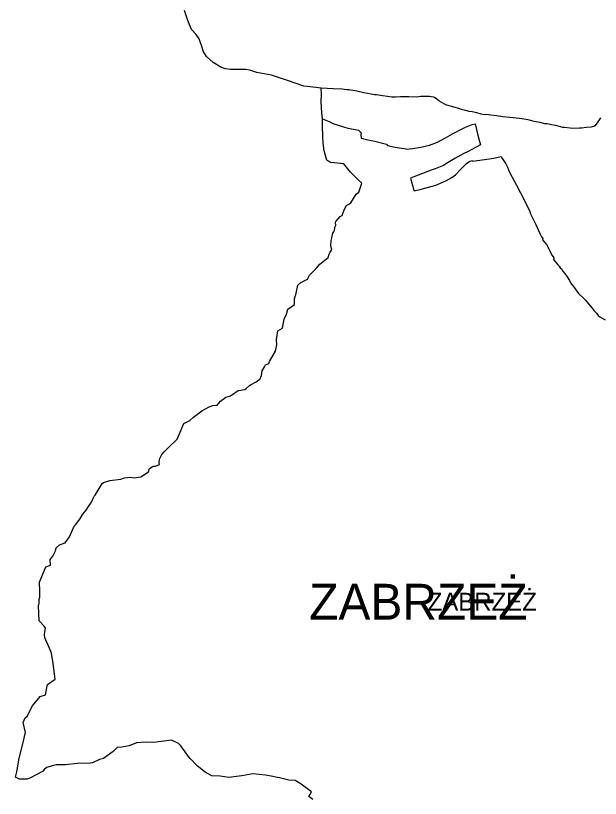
# Model space of a CAD drawing. Extents: x -562952 to -547638, y 190691 to 208158.
# Drawn here: x -562570 to -559633, y 198378 to 202309 of the extents above; entities that cross this region are included whole.
import ezdxf

# ---------------------------------------------------------------- set-up
doc = ezdxf.new("R2010")
doc.units = 0
for name, color, linetype in [('granica_gminy', 7, 'Continuous'), ('granica_sołectwa', 7, 'Continuous'), ('nazwy miejscowości', 7, 'Continuous'), ('nazwy miejscowości DUŻE', 7, 'Continuous'), ('obwódka', 7, 'Continuous')]:
    doc.layers.add(name, color=color, linetype=linetype)

msp = doc.modelspace()

# ---------------------------------------------------------------- linework, layer by layer
at = {"layer": 'granica_gminy'}
msp.add_lwpolyline([(-561077.5, 198371.9), (-561096.6, 198387.6), (-561083.3, 198410), (-561135.6, 198449.1), (-561165.8, 198467.7), (-561197.6, 198469.7), (-561243.6, 198480.3), (-561254.1, 198482.6), (-561287, 198489.2), (-561314.3, 198494.3), (-561378.7, 198500.4), (-561432.9, 198490.8), (-561447.6, 198488.4), (-561498.1, 198482.4), (-561542, 198488.3), (-561584.2, 198491.4), (-561618.4, 198509.3), (-561658.1, 198541.3), (-561692.7, 198577.8), (-561704, 198590.1), (-561709.6, 198600), (-561740.1, 198642.1), (-561751.4, 198653.7), (-561787.4, 198669.6), (-561877, 198657.9), (-561914.9, 198659.3), (-561961.9, 198656.2), (-562000, 198640.9), (-562037, 198634.7), (-562059.7, 198632.3), (-562080, 198612.5), (-562129.3, 198578.4), (-562147.9, 198572.7), (-562184, 198556.7), (-562195.9, 198554.2), (-562261.3, 198552.7), (-562319.6, 198546), (-562353.3, 198545.9), (-562366, 198545.7), (-562387, 198541.1), (-562413.4, 198533), (-562424.9, 198524.3), (-562435.1, 198512.3), (-562495.8, 198481), (-562512.4, 198473.7), (-562551, 198474), (-562569.7, 198484.5), (-562564.2, 198510.5), (-562552.1, 198578.6), (-562529.2, 198670.8), (-562524.3, 198697.2), (-562519.7, 198708.4), (-562531.9, 198759), (-562521.7, 198782.3), (-562512, 198789.8), (-562484.5, 198842.9), (-562447.3, 198889.6), (-562419.1, 198897.7), (-562409.8, 198950), (-562371.2, 198976.2), (-562381.9, 199054.7), (-562389.4, 199106.5), (-562401.7, 199134.5), (-562423.7, 199184.4), (-562424.3, 199201.2), (-562425.6, 199204.1), (-562422.7, 199211.1), (-562422.1, 199221.8), (-562420.1, 199231.8), (-562425.9, 199241.6), (-562451.8, 199269.7), (-562453.4, 199308.8), (-562454.4, 199342.4), (-562452.1, 199358.3), (-562452.1, 199376.1), (-562448.9, 199387.8), (-562448.9, 199418.7), (-562450.2, 199464.1), (-562418, 199539.6), (-562395.3, 199549.6), (-562395.7, 199577.9), (-562382.2, 199594.8), (-562368.7, 199624.7), (-562369.7, 199626.3), (-562365.8, 199635.1), (-562348.8, 199650.5), (-562320.9, 199661.2), (-562299.2, 199690.7), (-562275.2, 199744), (-562268.9, 199751), (-562248.1, 199779.7), (-562232, 199805.4), (-562216.2, 199825), (-562203.6, 199842.8), (-562188.7, 199865.5), (-562176.4, 199891.7), (-562175.8, 199895.6), (-562170.6, 199899.8), (-562136, 199958.9), (-562127.9, 199964.7), (-562096.9, 199974.8), (-562041.6, 199980.3), (-562022.8, 199988), (-561992.3, 199990.5), (-561973.6, 199987.4), (-561940.6, 199991.9), (-561902.1, 200017.2), (-561896.6, 200034.7), (-561883.6, 200043.4), (-561879, 200045.5), (-561867.7, 200046.6), (-561846.9, 200054), (-561849.2, 200062.8), (-561847.5, 200081.5), (-561835.5, 200104.6), (-561823.3, 200118.3), (-561802.3, 200139.2), (-561758.3, 200182.2), (-561724.9, 200260.6), (-561694.9, 200274.6), (-561676.6, 200292.5), (-561634.5, 200324.3), (-561597.6, 200344.8), (-561579.1, 200350.2), (-561557.5, 200352.5), (-561541.3, 200371.8), (-561513.6, 200393.1), (-561490.3, 200399.2), (-561452.8, 200425.9), (-561419, 200431.3), (-561412.2, 200435.4), (-561395.1, 200451.8), (-561387, 200455.9), (-561362.3, 200470.4), (-561344, 200482.3), (-561337.6, 200492.7), (-561334.9, 200502.2), (-561332.2, 200525.2), (-561319.4, 200544.8), (-561315, 200554.6), (-561297.2, 200561.6), (-561293.8, 200572.4), (-561265.1, 200622.8), (-561258.3, 200655.2), (-561260.3, 200681.6), (-561252.8, 200725.8), (-561228.9, 200739.9), (-561220.4, 200785.2), (-561208.6, 200810.2), (-561203.2, 200833.9), (-561169.5, 200858.4), (-561169.1, 200886.5), (-561161, 200914.8), (-561151.9, 200955.1), (-561138, 200968.3), (-561103, 200984.7), (-561094.2, 201006), (-561065.1, 201034.1), (-561060.7, 201038.8), (-561041.4, 201059.8), (-561000.6, 201094.1), (-560995.2, 201111.4), (-560990.8, 201116.8), (-560981.7, 201134), (-560986.5, 201150.5), (-560985.1, 201178.7), (-560981, 201193), (-560977.1, 201216.9), (-560973.1, 201220.7), (-560968.2, 201230.6), (-560966.1, 201240.7), (-560967.5, 201243.1), (-560961.4, 201255.9), (-560962.8, 201267.8), (-560960.8, 201274.2), (-560940.4, 201299.9), (-560929, 201305.4), (-560919.5, 201333.6), (-560908.3, 201354.9), (-560895.3, 201362.2), (-560886.3, 201369.5), (-560858.5, 201411.4), (-560846.4, 201421.6), (-560830.3, 201466.9), (-560847.8, 201482.2), (-560880.8, 201515.7), (-560887.3, 201523.2), (-560921.9, 201564.6), (-560986, 201570.9), (-561002.2, 201580.3), (-561006.1, 201582.7), (-561013.7, 201606.9), (-561021.3, 201636.3), (-561021.6, 201641.6), (-561024.5, 201669.4), (-561026.8, 201700.8), (-561027, 201706), (-561028, 201750.2), (-561029, 201791.4), (-561031.9, 201821.3), (-561035.7, 201876.1), (-561033.9, 201914.4), (-561034.7, 201943.8), (-561104.3, 201952.6), (-561121.7, 201955.4), (-561204.9, 201983.5), (-561283.9, 202009.4), (-561302.4, 202012.7), (-561357.7, 202023.9), (-561394.2, 202034.9), (-561415.3, 202038.1), (-561491.3, 202038.8), (-561515.8, 202041.5), (-561539.8, 202050.1), (-561578.3, 202073.8), (-561611.2, 202103.1), (-561627.6, 202130.9), (-561632.2, 202148.6), (-561648.7, 202192.9), (-561663.3, 202213.4), (-561686.7, 202239.4), (-561705.3, 202285), (-561722.3, 202335.3)], dxfattribs=at)
at = {"layer": 'granica_sołectwa'}
for points in [[(-560702.2, 201902.1), (-560727.2, 201906), (-560746.9, 201909.6), (-560756.6, 201910.4), (-560767.7, 201910.4), (-560783.5, 201914.6), (-560820.9, 201921.5), (-560856.5, 201929), (-560896.9, 201935.5), (-560906.8, 201935.5), (-560919.6, 201938.5), (-560929.2, 201939.4), (-560974.1, 201941.8), (-561034.7, 201943.8)], [(-560343.5, 201842.3), (-560368.1, 201848.9), (-560379.4, 201853), (-560392.3, 201855.4), (-560409.6, 201861.4), (-560420.9, 201867.1), (-560443.9, 201880.9), (-560452.6, 201886.9), (-560462.2, 201896.1), (-560469.4, 201900), (-560481.9, 201901.5), (-560490.3, 201903.6), (-560510.6, 201903.3), (-560535.1, 201903), (-560556.9, 201900), (-560594.2, 201900.3), (-560636.1, 201900.3), (-560661.8, 201899.1), (-560680.9, 201899.7), (-560702.2, 201902.1)], [(-559632.5, 201795), (-559648.3, 201770.8), (-559660.3, 201754.6), (-559665.3, 201751.3), (-559679.1, 201748), (-559704.5, 201747.1), (-559726.1, 201744.1), (-559737.1, 201743.8), (-559772, 201742.3), (-559784.6, 201744.1), (-559813, 201746.8), (-559821.7, 201747.7), (-559856.9, 201756.4), (-559878.4, 201760.3), (-559899.9, 201766.3), (-559911.3, 201766), (-559937.3, 201771.4), (-559955.6, 201774.9), (-559965.7, 201777), (-559988.7, 201784.5), (-560004.9, 201787.2), (-560039.6, 201792.3), (-560087.7, 201796.8), (-560123, 201801.3), (-560154.1, 201804.9), (-560182.8, 201808.5), (-560193, 201810), (-560208.1, 201811.7), (-560216.2, 201810), (-560230.6, 201814.1), (-560253, 201821), (-560276.6, 201825.5), (-560292.2, 201827.9), (-560308.3, 201832.7), (-560325, 201836.3), (-560343.5, 201842.3)], [(-561029, 201791.4), (-560994.8, 201777.7), (-560976.4, 201767.3), (-560923.1, 201749.9), (-560900.6, 201744.5), (-560872.5, 201738), (-560847, 201733.8), (-560834.7, 201719.7), (-560835.9, 201711.3), (-560833.8, 201693.3)], [(-560834.3, 201694), (-560821, 201689.4), (-560800.3, 201684.9), (-560783.2, 201681.6), (-560764.8, 201678.6), (-560707.4, 201663.5), (-560702.6, 201657.4), (-560663.6, 201647.5), (-560610.6, 201639.1), (-560606.3, 201638.9), (-560575.8, 201641.8), (-560534.7, 201648.5), (-560491.2, 201658.8), (-560451.4, 201673.2), (-560410.8, 201695.2), (-560375.5, 201715.4), (-560323.6, 201741.4), (-560310.2, 201748.3), (-560276.2, 201762), (-560262.1, 201766.2), (-560247.4, 201709.3), (-560241.6, 201682.8), (-560234, 201659.3), (-560299.9, 201624.2), (-560318.7, 201616.2), (-560363.3, 201591.1), (-560406.2, 201565.6), (-560420.1, 201557), (-560462.2, 201539.3), (-560482.3, 201532.2), (-560570.2, 201499.9), (-560587, 201492.2), (-560569.3, 201432.9), (-560568.5, 201428.2), (-560532.7, 201436.6), (-560458.7, 201457.3), (-560408.9, 201479.2), (-560378.7, 201495.8), (-560359.8, 201509.3), (-560331.6, 201539.8), (-560304.7, 201566.3), (-560288.8, 201578.3), (-560275.3, 201581.1), (-560273.8, 201577.7), (-560214, 201585.8), (-560168.3, 201593.4), (-560131, 201602.2), (-560124.7, 201589), (-560108, 201565.3), (-560098.9, 201547.1), (-560093.4, 201534.2), (-560085, 201516)], [(-560765.4, 201677.3), (-560765.4, 201677.3)], [(-560085, 201516), (-560054.5, 201458), (-560012.8, 201376.7), (-559999.6, 201352.2), (-559989.2, 201329.5), (-559983.3, 201313.6), (-559957.1, 201259.1), (-559937.1, 201214.8), (-559929, 201198.6), (-559922.4, 201190.1), (-559922.5, 201183.4), (-559903.7, 201159.4), (-559874.3, 201104.1), (-559866.5, 201092.4), (-559867.5, 201084.3), (-559845.8, 201057.1), (-559839.6, 201050), (-559835.1, 201042.3), (-559827, 201034.8), (-559822.4, 201027), (-559810.4, 201013.1), (-559799.1, 200996.3), (-559788.3, 200978.4), (-559782.1, 200966.4), (-559768.3, 200948.6), (-559741.7, 200913.2), (-559717.1, 200890.6), (-559706.5, 200879), (-559675.6, 200841.9), (-559663.9, 200826.2), (-559652.5, 200815.3), (-559643.1, 200802.2), (-559636.1, 200795.9), (-559608.9, 200780.4)]]:
    msp.add_lwpolyline(points, dxfattribs=at)
at = {"layer": 'obwódka'}
msp.add_lwpolyline([(-561077.5, 198371.9), (-561096.6, 198387.6), (-561083.3, 198410), (-561135.6, 198449.1), (-561165.8, 198467.7), (-561197.6, 198469.7), (-561243.6, 198480.3), (-561254.1, 198482.6), (-561287, 198489.2), (-561314.3, 198494.3), (-561378.7, 198500.4), (-561432.9, 198490.8), (-561447.6, 198488.4), (-561498.1, 198482.4), (-561542, 198488.3), (-561584.2, 198491.4), (-561618.4, 198509.3), (-561658.1, 198541.3), (-561692.7, 198577.8), (-561704, 198590.1), (-561709.6, 198600), (-561740.1, 198642.1), (-561751.4, 198653.7), (-561787.4, 198669.6), (-561877, 198657.9), (-561914.9, 198659.3), (-561961.9, 198656.2), (-562000, 198640.9), (-562037, 198634.7), (-562059.7, 198632.3), (-562080, 198612.5), (-562129.3, 198578.4), (-562147.9, 198572.7), (-562184, 198556.7), (-562195.9, 198554.2), (-562261.3, 198552.7), (-562319.6, 198546), (-562353.3, 198545.9), (-562366, 198545.7), (-562387, 198541.1), (-562413.4, 198533), (-562424.9, 198524.3), (-562435.1, 198512.3), (-562495.8, 198481), (-562512.4, 198473.7), (-562551, 198474), (-562569.7, 198484.5), (-562564.2, 198510.5), (-562552.1, 198578.6), (-562529.2, 198670.8), (-562524.3, 198697.2), (-562519.7, 198708.4), (-562531.9, 198759), (-562521.7, 198782.3), (-562512, 198789.8), (-562484.5, 198842.9), (-562447.3, 198889.6), (-562419.1, 198897.7), (-562409.8, 198950), (-562371.2, 198976.2), (-562381.9, 199054.7), (-562389.4, 199106.5), (-562401.7, 199134.5), (-562423.7, 199184.4), (-562424.3, 199201.2), (-562425.6, 199204.1), (-562422.7, 199211.1), (-562422.1, 199221.8), (-562420.1, 199231.8), (-562425.9, 199241.6), (-562451.8, 199269.7), (-562453.4, 199308.8), (-562454.4, 199342.4), (-562452.1, 199358.3), (-562452.1, 199376.1), (-562448.9, 199387.8), (-562448.9, 199418.7), (-562450.2, 199464.1), (-562418, 199539.6), (-562395.3, 199549.6), (-562395.7, 199577.9), (-562382.2, 199594.8), (-562368.7, 199624.7), (-562369.7, 199626.3), (-562365.8, 199635.1), (-562348.8, 199650.5), (-562320.9, 199661.2), (-562299.2, 199690.7), (-562275.2, 199744), (-562268.9, 199751), (-562248.1, 199779.7), (-562232, 199805.4), (-562216.2, 199825), (-562203.6, 199842.8), (-562188.7, 199865.5), (-562176.4, 199891.7), (-562175.8, 199895.6), (-562170.6, 199899.8), (-562136, 199958.9), (-562127.9, 199964.7), (-562096.9, 199974.8), (-562041.6, 199980.3), (-562022.8, 199988), (-561992.3, 199990.5), (-561973.6, 199987.4), (-561940.6, 199991.9), (-561902.1, 200017.2), (-561896.6, 200034.7), (-561883.6, 200043.4), (-561879, 200045.5), (-561867.7, 200046.6), (-561846.9, 200054), (-561849.2, 200062.8), (-561847.5, 200081.5), (-561835.5, 200104.6), (-561823.3, 200118.3), (-561802.3, 200139.2), (-561758.3, 200182.2), (-561724.9, 200260.6), (-561694.9, 200274.6), (-561676.6, 200292.5), (-561634.5, 200324.3), (-561597.6, 200344.8), (-561579.1, 200350.2), (-561557.5, 200352.5), (-561541.3, 200371.8), (-561513.6, 200393.1), (-561490.3, 200399.2), (-561452.8, 200425.9), (-561419, 200431.3), (-561412.2, 200435.4), (-561395.1, 200451.8), (-561387, 200455.9), (-561362.3, 200470.4), (-561344, 200482.3), (-561337.6, 200492.7), (-561334.9, 200502.2), (-561332.2, 200525.2), (-561319.4, 200544.8), (-561315, 200554.6), (-561297.2, 200561.6), (-561293.8, 200572.4), (-561265.1, 200622.8), (-561258.3, 200655.2), (-561260.3, 200681.6), (-561252.8, 200725.8), (-561228.9, 200739.9), (-561220.4, 200785.2), (-561208.6, 200810.2), (-561203.2, 200833.9), (-561169.5, 200858.4), (-561169.1, 200886.5), (-561161, 200914.8), (-561151.9, 200955.1), (-561138, 200968.3), (-561103, 200984.7), (-561094.2, 201006), (-561065.1, 201034.1), (-561060.7, 201038.8), (-561041.4, 201059.8), (-561000.6, 201094.1), (-560995.2, 201111.4), (-560990.8, 201116.8), (-560981.7, 201134), (-560986.5, 201150.5), (-560985.1, 201178.7), (-560981, 201193), (-560977.1, 201216.9), (-560973.1, 201220.7), (-560968.2, 201230.6), (-560966.1, 201240.7), (-560967.5, 201243.1), (-560961.4, 201255.9), (-560962.8, 201267.8), (-560960.8, 201274.2), (-560940.4, 201299.9), (-560929, 201305.4), (-560919.5, 201333.6), (-560908.3, 201354.9), (-560895.3, 201362.2), (-560886.3, 201369.5), (-560858.5, 201411.4), (-560846.4, 201421.6), (-560830.3, 201466.9), (-560847.8, 201482.2), (-560880.8, 201515.7), (-560887.3, 201523.2), (-560921.9, 201564.6), (-560986, 201570.9), (-561002.2, 201580.3), (-561006.1, 201582.7), (-561013.7, 201606.9), (-561021.3, 201636.3), (-561021.6, 201641.6), (-561024.5, 201669.4), (-561026.8, 201700.8), (-561027, 201706), (-561028, 201750.2), (-561029, 201791.4), (-561031.9, 201821.3), (-561035.7, 201876.1), (-561033.9, 201914.4), (-561034.7, 201943.8), (-561104.3, 201952.6), (-561121.7, 201955.4), (-561204.9, 201983.5), (-561283.9, 202009.4), (-561302.4, 202012.7), (-561357.7, 202023.9), (-561394.2, 202034.9), (-561415.3, 202038.1), (-561491.3, 202038.8), (-561515.8, 202041.5), (-561539.8, 202050.1), (-561578.3, 202073.8), (-561611.2, 202103.1), (-561627.6, 202130.9), (-561632.2, 202148.6), (-561648.7, 202192.9), (-561663.3, 202213.4), (-561686.7, 202239.4), (-561705.3, 202285), (-561722.3, 202335.3)], dxfattribs=at)

# ---------------------------------------------------------------- texts
at = {"layer": 'nazwy miejscowości'}
msp.add_text('ZABRZEŻ', height=90, dxfattribs=at).set_placement((-560500.2, 199320.1))
at = {"layer": 'nazwy miejscowości DUŻE'}
msp.add_text('ZABRZEŻ', height=180, dxfattribs=at).set_placement((-561095.2, 199275.1))

doc.saveas('drawing.dxf')
